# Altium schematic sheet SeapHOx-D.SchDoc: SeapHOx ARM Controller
size Letter; PageSetup: Record=PageOptions¦CenterHorizontal=True¦CenterVertical=True¦PrintScale=0.94¦XCorrection=1.00¦YCorrection=1.00¦PrintKind=1¦BorderSize=5000000¦LeftOffset=0¦BottomOffset=0¦Orientation=2¦PaperLength=1000¦PaperWidth=1000¦Scale=100¦PaperSource=7¦PrintQuality=-4¦MediaType=1¦DitherType=10¦PaperKind=Letter¦PrintScaleMode=1
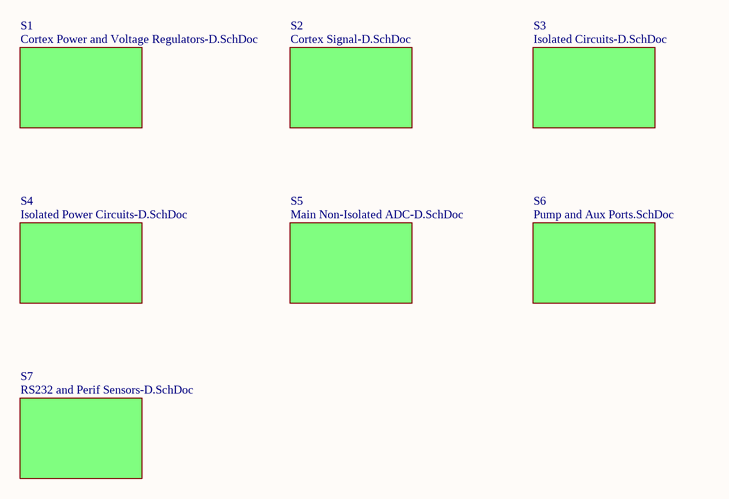
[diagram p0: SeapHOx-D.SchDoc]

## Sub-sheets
S1 = Cortex Power and Voltage Regulators-D.SchDoc: no entries
S2 = Cortex Signal-D.SchDoc: no entries
S3 = Isolated Circuits-D.SchDoc: no entries
S4 = Isolated Power Circuits-D.SchDoc: no entries
S5 = Main Non-Isolated ADC-D.SchDoc: no entries
S6 = Pump and Aux Ports.SchDoc: no entries
S7 = RS232 and Perif Sensors-D.SchDoc: no entries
